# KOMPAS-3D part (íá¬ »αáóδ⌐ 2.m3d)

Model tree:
1. Эскиз:1
2. Операция выдавливания:1
     Расстояние 1 = 11
3. Эскиз:2
4. Вырезать элемент выдавливания:1
     Расстояние 1 = 34.8
5. Скругление:1
     Радиус = 1
6. Скругление:2
     Радиус = 2
7. Эскиз:3
8. Вырезать элемент выдавливания:2
     Расстояние 1 = 0.2
9. Скругление:3
     Радиус = 0.1
10. Эскиз:4
11. Операция выдавливания:2
     Расстояние 1 = 0.5; Расстояние 2 = 4.9
12. Скругление:4
     Радиус = 0.2
13. Эскиз:5
14. Операция выдавливания:3
     Расстояние 1 = 0.5; Расстояние 2 = 4.9

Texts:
  бак правый 2
  Сплав АЛ8  ГОСТ 1583-93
